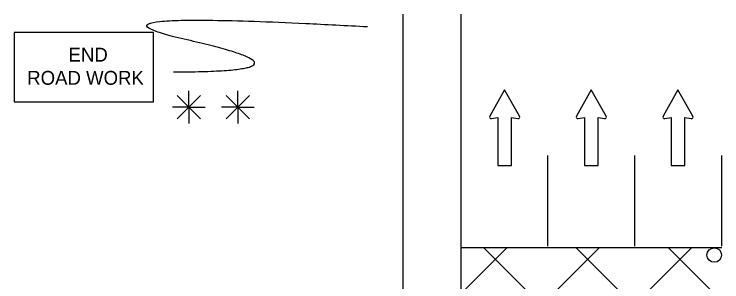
# Model space of a CAD drawing. Extents: x 16724 to 18475, y 7025 to 8210.
# Drawn here: x 16761.1 to 16956.3, y 8136.6 to 8210.4 of the extents above; entities that cross this region are included whole.
import ezdxf

# ---------------------------------------------------------------- set-up
doc = ezdxf.new("R2010")
doc.units = 0
for name, color, linetype in [('MT_SCRATCH_LEVEL_A', 7, 'Continuous'), ('MT_SCRATCH_LEVEL_E', 7, 'Continuous'), ('PAVT_EDGE_EX', 7, 'Continuous'), ('TRAFFIC_SIGNS_PR', 7, 'Continuous'), ('TYPICAL_TEXT_DIMEN_PR', 7, 'Continuous')]:
    doc.layers.add(name, color=color, linetype=linetype)

msp = doc.modelspace()

# ---------------------------------------------------------------- linework, layer by layer
at = {"layer": 'MT_SCRATCH_LEVEL_A'}
for p, q in [((16956.3, 8146.01), (16884.3, 8146.01)), ((16884.3, 8146.01), (16884.3, 8002.04)), ((16956.3, 8146.01), (16884.3, 8146.01)), ((16884.3, 8146.01), (16884.3, 8031.47)), ((16884.3, 8133.29), (16897.01, 8146.01)), ((16884.3, 8107.84), (16922.46, 8146.01)), ((16884.3, 8082.38), (16947.92, 8146.01)), ((16956.3, 8080.39), (16890.67, 8146.01)), ((16956.3, 8105.84), (16916.13, 8146.01)), ((16956.3, 8131.3), (16941.59, 8146.01))]:
    msp.add_line(p, q, dxfattribs=at)
at = {"layer": 'MT_SCRATCH_LEVEL_E'}
for p, q in [((16896.39, 8189.53), (16892.28, 8182.29)), ((16900.54, 8182.29), (16896.39, 8189.53)), ((16920.29, 8189.53), (16916.18, 8182.29)), ((16924.44, 8182.29), (16920.29, 8189.53)), ((16944.2, 8189.53), (16940.09, 8182.29)), ((16948.34, 8182.29), (16944.2, 8189.53)), ((16892.76, 8181.61), (16894.54, 8181.92)), ((16894.54, 8181.92), (16894.54, 8168.67)), ((16898.28, 8168.67), (16898.28, 8181.92)), ((16898.28, 8181.92), (16900.06, 8181.61)), ((16916.66, 8181.61), (16918.44, 8181.92)), ((16918.44, 8181.92), (16918.44, 8168.67)), ((16922.18, 8168.67), (16922.18, 8181.92)), ((16922.18, 8181.92), (16923.96, 8181.61)), ((16940.57, 8181.61), (16942.35, 8181.92)), ((16942.35, 8181.92), (16942.35, 8168.67)), ((16946.09, 8168.67), (16946.09, 8181.92)), ((16946.09, 8181.92), (16947.87, 8181.61)), ((16894.54, 8168.67), (16898.28, 8168.67)), ((16918.44, 8168.67), (16922.18, 8168.67)), ((16942.35, 8168.67), (16946.09, 8168.67))]:
    msp.add_line(p, q, dxfattribs=at)
for centre, start, end in [((16892.69, 8182.07), 150.4248, 279.9638), ((16900.13, 8182.07), 260.0362, 29.7731), ((16916.59, 8182.07), 150.4248, 279.9638), ((16924.03, 8182.07), 260.0362, 29.7731), ((16940.49, 8182.07), 150.4248, 279.9638), ((16947.93, 8182.07), 260.0362, 29.7731)]:
    msp.add_arc(centre, 0.463, start, end, dxfattribs=at)
at = {"layer": 'PAVT_EDGE_EX'}
for p, q in [((16868.3, 8210.42), (16868.3, 7546.41)), ((16884.3, 8210.42), (16884.3, 7546.41))]:
    msp.add_line(p, q, dxfattribs=at)
for points in [[(16908.3, 8146.41), (16908.3, 8171.41)], [(16932.3, 8146.41), (16932.3, 8171.41)], [(16956.3, 8146.41), (16956.3, 8171.41)]]:
    msp.add_lwpolyline(points, dxfattribs=at)
at = {"layer": 'TRAFFIC_SIGNS_PR'}
msp.add_lwpolyline([(16761.14, 8186.2), (16799.54, 8186.2), (16799.54, 8205.4), (16761.14, 8205.4)], close=True, dxfattribs=at)
msp.add_circle((16954.2, 8143.99), 2, dxfattribs=at)
msp.add_open_spline([(16805.07, 8194.51), (16847.58, 8194.51), (16771.06, 8211.92), (16858.6, 8206.98)], degree=2, dxfattribs=at)
at = {"layer": 'TYPICAL_TEXT_DIMEN_PR'}
for p, q in [((16809.32, 8184.77), (16809.32, 8189.23)), ((16822.83, 8184.77), (16822.83, 8189.23)), ((16812.51, 8187.96), (16806.13, 8181.59)), ((16806.14, 8187.96), (16812.51, 8181.59)), ((16819.64, 8187.96), (16826.02, 8181.59)), ((16826.02, 8187.96), (16819.64, 8181.59)), ((16809.32, 8184.77), (16804.79, 8184.77)), ((16809.32, 8184.77), (16812.51, 8184.77)), ((16809.32, 8184.77), (16813.8, 8184.77)), ((16809.32, 8184.77), (16809.32, 8180.27)), ((16822.83, 8184.77), (16818.3, 8184.77)), ((16822.83, 8184.77), (16826.02, 8184.77)), ((16822.83, 8184.77), (16827.31, 8184.77)), ((16822.83, 8184.77), (16822.83, 8180.27))]:
    msp.add_line(p, q, dxfattribs=at)

# ---------------------------------------------------------------- texts
at = {"layer": 'TRAFFIC_SIGNS_PR'}
for s, p in [('END', (16776.15, 8197.33)), ('ROAD WORK', (16764.75, 8190.94))]:
    msp.add_text(s, height=3.831, dxfattribs=at).set_placement(p)

doc.saveas('drawing.dxf')
